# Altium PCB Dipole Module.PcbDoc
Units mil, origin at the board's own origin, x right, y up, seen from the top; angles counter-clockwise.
Board outline 1850 x 1950 mil, 2 copper layers (Top, Bottom), stack 62.8 mil thick; 30 components, 36 nets, 170 pads, 0 vias.
Unrouted connection lines stored in the file: 1.
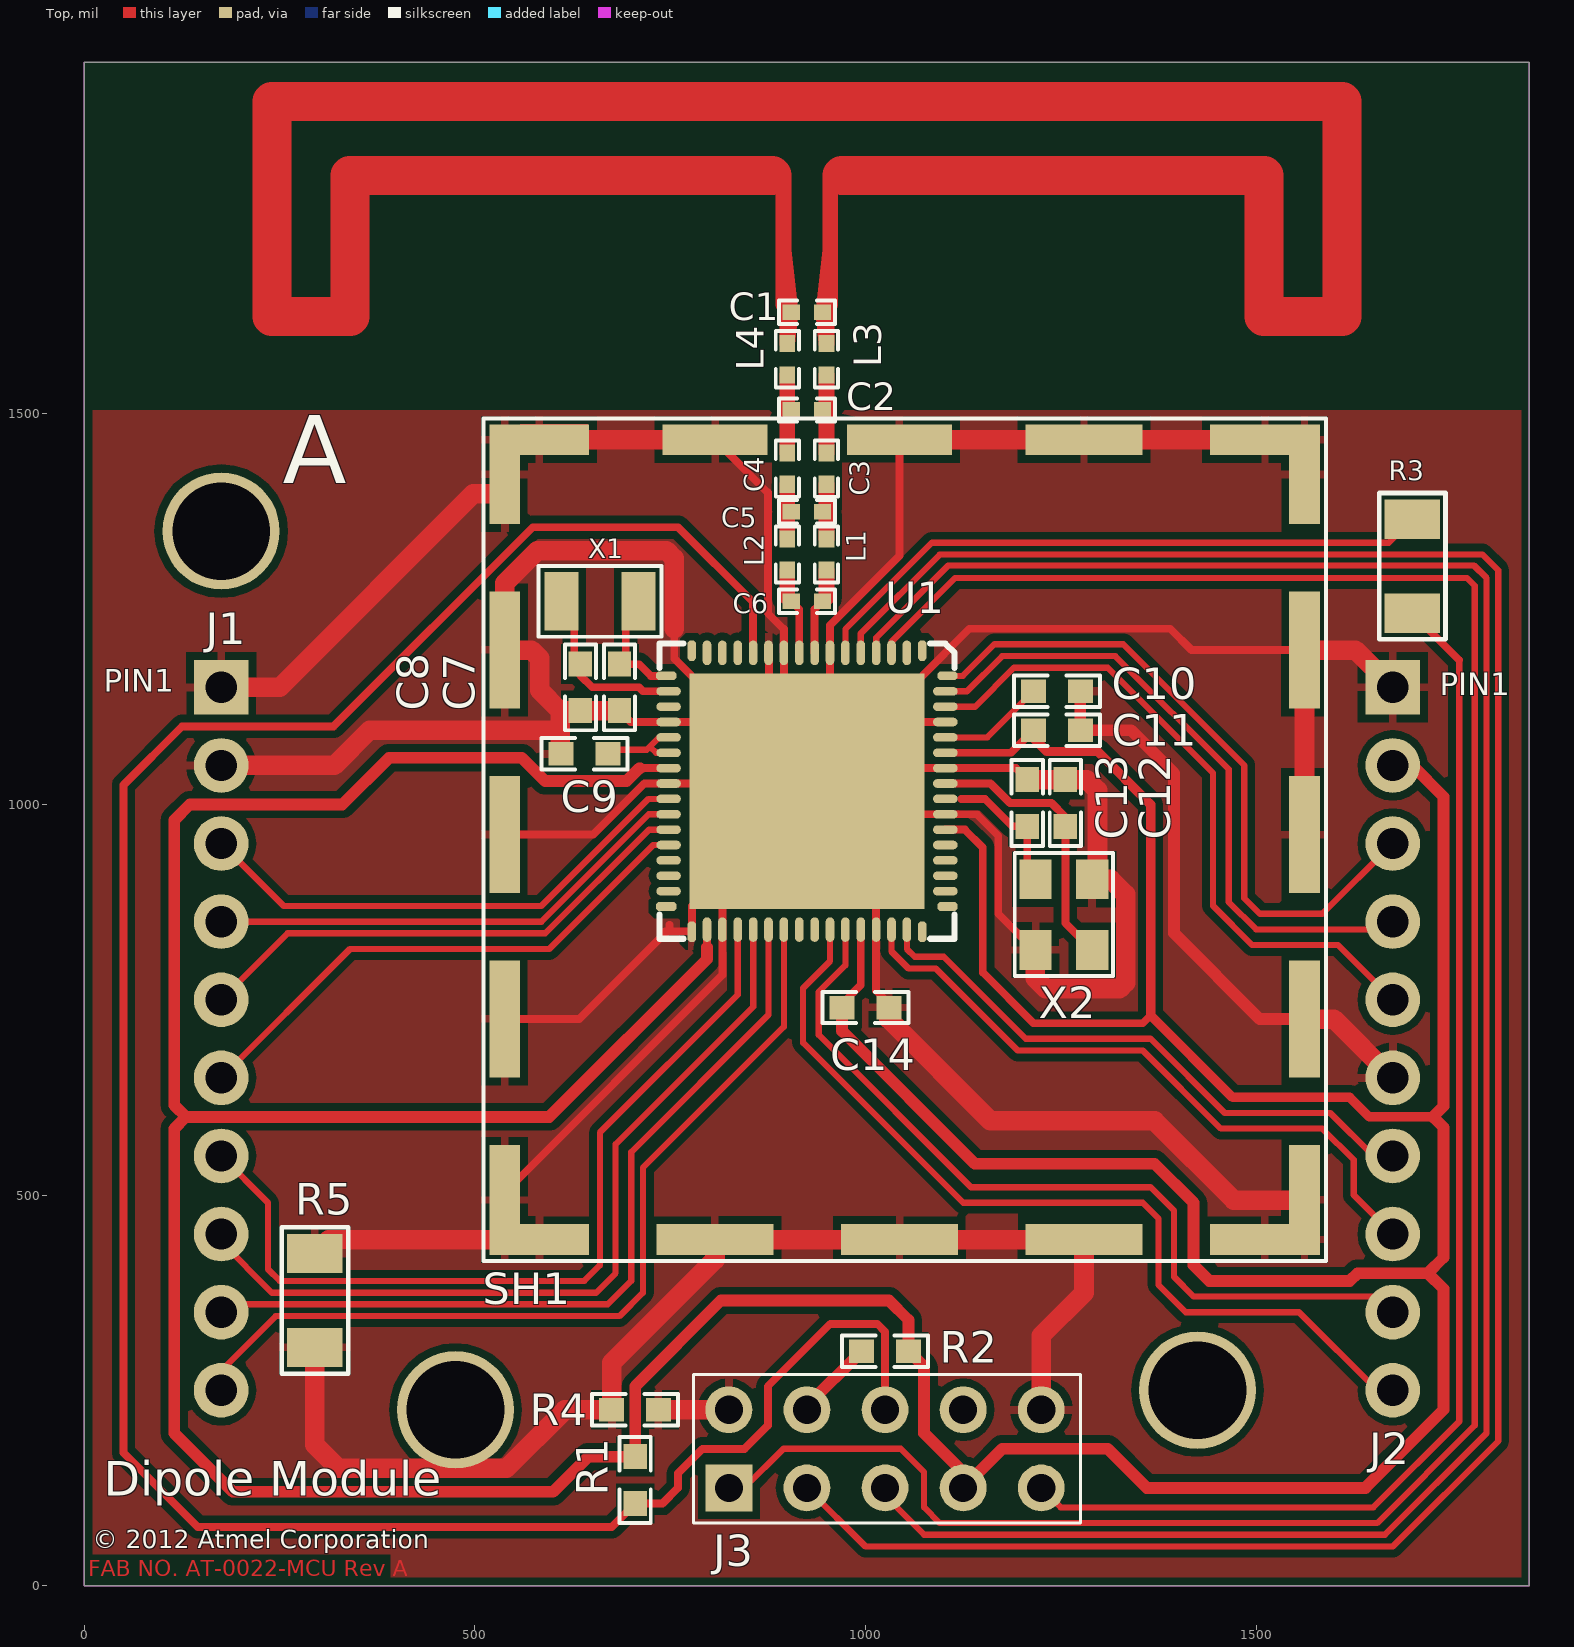
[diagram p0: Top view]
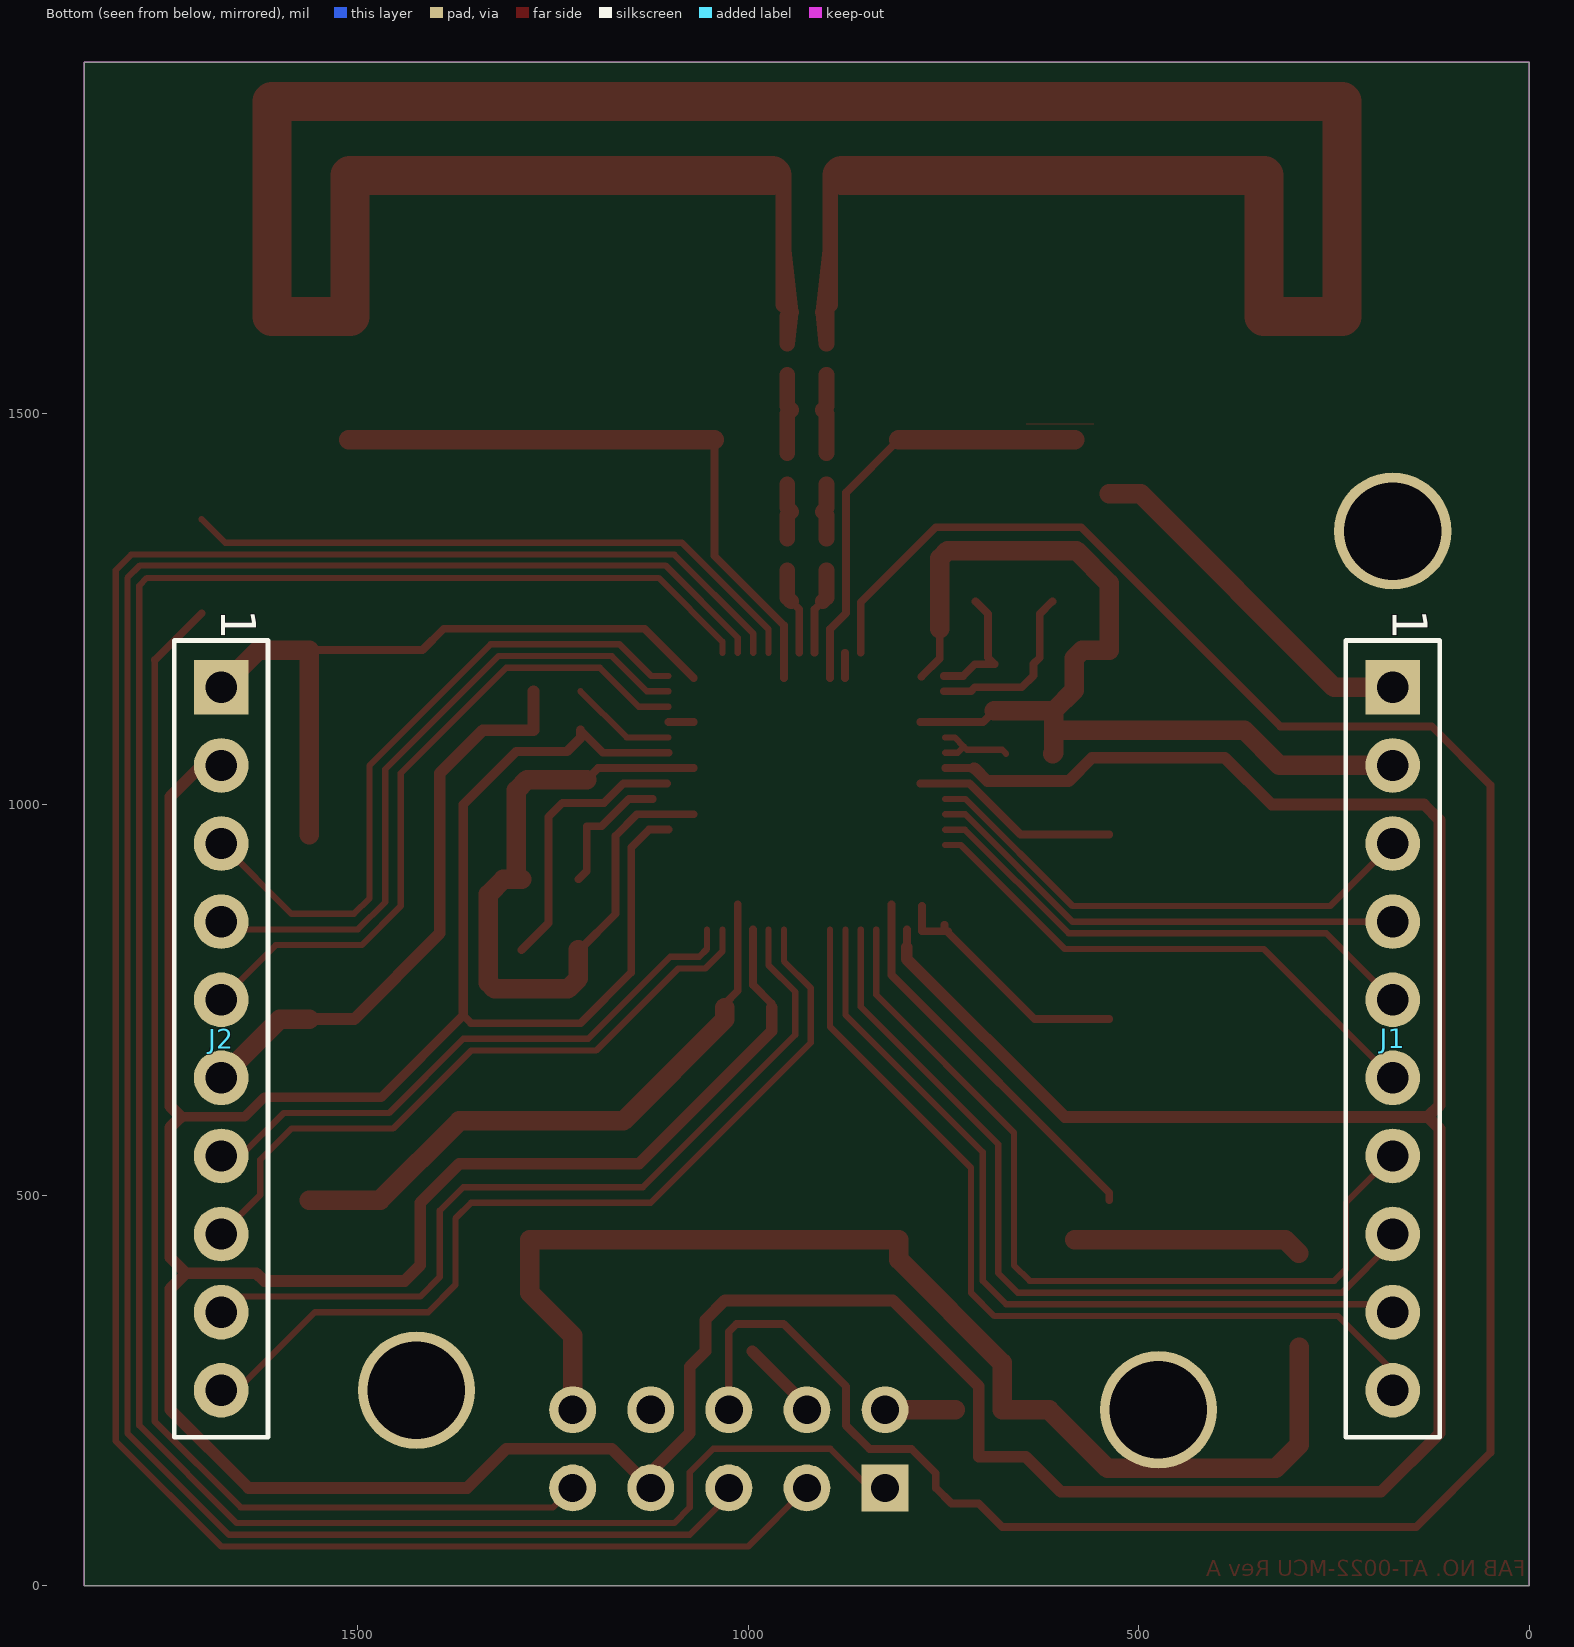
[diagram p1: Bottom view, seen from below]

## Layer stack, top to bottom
Top: signal copper 1.4
Dielectric: dielectric 60, FR-4, Dk 4
Bottom: signal copper 1.4

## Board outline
0,1950 1850,1950 1850,0 0,0

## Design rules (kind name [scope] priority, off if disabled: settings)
Clearance [All] p1: gap=10
DiffPairsRouting [All] p1 off: maxlimit=10 minlimit=10 mostfreqgap=10 maxuncoupledlength=500
FanoutControl Fanout_BGA [IsBGA] p1 off: bgadir=Out bgaviamode=Centered fanoutstyle=Auto fanoutdirection=Alternating viagrid=1 // Fanout_BGA (Default Rule)
FanoutControl Fanout_LCC [IsLCC] p2 off: bgadir=Out bgaviamode=Centered fanoutstyle=Auto fanoutdirection=Alternating viagrid=1 // Fanout_LCC (Default Rule)
FanoutControl Fanout_SOIC [IsSOIC] p3 off: bgadir=Out bgaviamode=Centered fanoutstyle=Auto fanoutdirection=Alternating viagrid=1 // Fanout_SOIC (Default Rule)
FanoutControl Fanout_Small [(CompPinCount < 5)] p4 off: bgadir=Out bgaviamode=Centered fanoutstyle=Auto fanoutdirection=OutThenIn viagrid=1 // Fanout_Small (Default Rule)
FanoutControl Fanout_Default [All] p5 off: bgadir=Out bgaviamode=Centered fanoutstyle=Auto fanoutdirection=Alternating viagrid=1 // Fanout_Default (Default Rule)
HoleSize [All] p1: absolutevalues=TRUE maxlimit=200 minlimit=1 maxpercent=80.000 minpercent=20.000
MinimumSolderMaskSliver [All] p1 off: minsoldermaskwidth=10
NetAntennae [All] p1 off: netantennaetolerance=0
PlaneConnect "Power Plane Connect Style - pads with no thermal" [(Name='J1-11') Or (Name='J1-12') Or (Name='J1-13') Or (Name='J1-14') Or (Name='J1-15') Or (Name='J1-16') Or (Name='J1-17') Or (Name='J1-18') Or (Name='J1-19') Or (Name='J1-20')] p1: planeconnectstyle=NoConnect reliefexpansion=20 reliefentries=4 reliefconductorwidth=10 reliefairgap=10 // PAD - No Thermal Connect Rule
PlaneConnect "Power Plane Connect Style - from global settings" [All] p2: planeconnectstyle=Relief reliefexpansion=20 reliefentries=2 reliefconductorwidth=8 reliefairgap=10
PolygonConnect [All] p1: connectstyle=Relief reliefconductorwidth=10 reliefentries=4 polygonreliefangle="90 Angle"
RoomDefinition "Dipole Module" [InComponentClass('Dipole Module')] p1: confinementstyle=ConfineIn formatcopy=TRUE lockcomponents=FALSE outline -9202.24,-8268.11 -7202.24,-8268.11 -7202.24,-7268.11 -9202.24,-7268.11
RoutingVias [All] p1: holewidth=28 width=50 viastyle="Through Hole" minholewidth=28 minwidth=50 maxholewidth=28 maxwidth=50
SilkToSilkClearance [All] p1: silktosilkclearance=1
SilkscreenOverComponentPads [All] p1 off: minsilkscreentomaskgap=10
SolderMaskExpansion "Solder Mask Expansion from CAM settings" [All] p1: expansion=2
Width [All] p1: maxlimit=100 minlimit=8 preferedwidth=10
16 further rules are at their usual default settings.

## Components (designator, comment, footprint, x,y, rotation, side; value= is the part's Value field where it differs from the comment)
C1 "NP" 0402 925,1630 r0 top
C2 "0.3pF" 0402 925,1505 r180 top
C3 "8.2pF" 0402 950,1430 r270 top locked
C4 "8.2pF" 0402 900,1430 r270 top locked
C5 "1pF" 0402-POL 925,1375 r180 top locked
C6 "0.7pF" 0402 925,1260 r180 top locked
C7 "12pF" 0603 685,1150 r270 top
C8 "12pF" 0603 635,1150 r270 top
C9 "X5R" 0603 640,1065 r180 top
C10 "X5R" 0603 1245,1145 r180 top
C11 "X5R" 0603 1245,1095 r180 top
C12 "12pF" 0603 1255.84,1001.84 r90 top
C13 "12pF" 0603 1207,1002 r270 top
C14 "X5R" 0603 1000,740 r0 top
J1 "Header 10" HDR1X10 175,1150 r270 bottom locked
J2 "Header 10" HDR1X10 1675,1150 r270 bottom locked
J3 "Header 5X2" HDR2X5 825,125 r90 top
L1 "LQG15HN2N7S02" 0402-POL 950,1320 r270 top locked
L2 "LQG15HN2N7S02" 0402-POL 900,1320 r270 top locked
L3 "LQG15HN1N0S02" 0402-POL 950,1570 r270 top
L4 "LQG15HN1N0S02" 0402-POL 900,1570 r270 top
R1 "0.5" 0603 705,135 r270 top
R2 "0.5" 0603 1025,300 r180 top
R3 "0.5" 1206_JUMPER 1700,1305 r90 top
R4 "0.5" 0603 705,225 r180 top
R5 "0.5" 1206_JUMPER 295,365 r90 top
SH1 "SHIELD" SHIELD_BMI-S-103_LAIRD 1050,955 r90 top locked
U1 "ATmega128RFA1-DE" MLF64-M2 925,1017 r90 top
X1 "32.768 KHZ" XTAL32_768KHZ_ABRACON 660,1260 r0 top
X2 "16.000 MHz 3.2 x 2.5 mm" XTAL16MHZKYOCERA 1254,859 r90 top

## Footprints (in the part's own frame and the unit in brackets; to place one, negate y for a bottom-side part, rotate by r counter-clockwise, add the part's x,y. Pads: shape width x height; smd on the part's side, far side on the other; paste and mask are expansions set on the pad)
0402 [mil]
  rect 22x20 smd: 1(-20,0) 2(20,0)
  silkscreen extent -36,-15 36,15
0402-POL [mil]
  rect 22x20 smd: 1(-20,0) 2(20,0)
  silkscreen extent -36,-15 36,15
0603 [mil]
  rect 32x30 smd: 1(-30,0) 2(30,0)
  silkscreen extent -55,-20 55,20
1206_JUMPER [mm]
  rect 1.27x1.8 smd: 1(-1.528,0.001) 2(1.528,-0.001)
  silkscreen extent -2.38,-1.08 2.38,1.08
HDR1X10 [mil] "HDR1X10"
  rect 70x70 hole 40: 1(0,0)
  round 70 hole 40: 2(100,0) 3(200,0) 4(300,0) 5(400,0) 6(500,0) 7(600,0) 8(700,0) 9(800,0) 10(900,0)
  silkscreen extent -60,-60 960,60
HDR2X5 [mil]
  rect 60x60 hole 36: 1(0,0)
  round 60 hole 36: 2(100,0) 3(0,-100) 4(100,-100) 5(0,-200) 6(100,-200) 7(0,-300) 8(100,-300) 9(0,-400) 10(100,-400)
  silkscreen extent -45,-450 145,45
MLF64-M2 [mm]
  oct 0.66x0.28 smd paste-0.03 mask+0: 1(4.572,-3.75) 16(4.572,3.75) 33(-4.572,3.75) 48(-4.572,-3.75)
  oval 0.8x0.28 smd paste-0.03 mask+0: 2(4.5,-3.25) 3(4.5,-2.75) 4(4.5,-2.25) 5(4.5,-1.75) 6(4.5,-1.25) 7(4.5,-0.75) 8(4.5,-0.25) 9(4.5,0.25) 10(4.5,0.75) 11(4.5,1.25) 12(4.5,1.75) 13(4.5,2.25) 14(4.5,2.75) 15(4.5,3.25) 34(-4.5,3.25) 35(-4.5,2.75) 36(-4.5,2.25) 37(-4.5,1.75) 38(-4.5,1.25) 39(-4.5,0.75) 40(-4.5,0.25) 41(-4.5,-0.25) 42(-4.5,-0.75) 43(-4.5,-1.25) 44(-4.5,-1.75) 45(-4.5,-2.25) 46(-4.5,-2.75) 47(-4.5,-3.25)
  oct 0.28x0.66 smd paste-0.03 mask+0: 17(3.75,4.572) 32(-3.75,4.572) 49(-3.75,-4.572) 64(3.75,-4.572)
  oval 0.28x0.8 smd paste-0.03 mask+0: 18(3.25,4.5) 19(2.75,4.5) 20(2.25,4.5) 21(1.75,4.5) 22(1.25,4.5) 23(0.75,4.5) 24(0.25,4.5) 25(-0.25,4.5) 26(-0.75,4.5) 27(-1.25,4.5) 28(-1.75,4.5) 29(-2.25,4.5) 30(-2.75,4.5) 31(-3.25,4.5) 50(-3.25,-4.5) 51(-2.75,-4.5) 52(-2.25,-4.5) 53(-1.75,-4.5) 54(-1.25,-4.5) 55(-0.75,-4.5) 56(-0.25,-4.5) 57(0.25,-4.5) 58(0.75,-4.5) 59(1.25,-4.5) 60(1.75,-4.5) 61(2.25,-4.5) 62(2.75,-4.5) 63(3.25,-4.5)
  rect 7.65x7.65 smd paste-2.8 mask+0: 65(0,0)
  silkscreen extent -4.8,-4.8 4.8,4.8
SHIELD_BMI-S-103_LAIRD [mm]
  rect 1x3.57 smd: 1(-13.005,-11.72) 5(13.005,-11.72)
  rect 3.57x1 smd: 1(-11.72,-13.005) 13(-11.72,13.005)
  rect 3.8x1 smd: 2(-5.835,-13.005) 3(0.165,-13.005) 4(6.165,-13.005) 10(6.165,13.005) 11(0.165,13.005) 12(-5.835,13.005)
  rect 3.24x1 smd: 5(11.885,-13.005) 9(11.885,13.005)
  rect 1x3.8 smd: 6(13.005,-5.835) 14(-13.005,6.165) 15(-13.005,0.165) 16(-13.005,-5.835)
  rect 1x3.4 smd: 7(13.005,0.165) 8(13.005,6.165)
  rect 1x3.24 smd: 9(13.005,11.885) 13(-13.005,11.885)
  Top lines w0.001: 13.505,12.505 13.505,10.305
  silkscreen extent -13.7,-13.7 13.7,13.7
XTAL16MHZKYOCERA [mm]
  rect 1.3x1.05 smd: 1(-1.15,0.925) 2(-1.15,-0.925) 3(1.15,0.925) 4(1.15,-0.925)
  silkscreen extent -2,-1.6 2,1.6
XTAL32_768KHZ_ABRACON [mm]
  rect 1.1x1.9 smd: 1(-1.25,0) 2(1.25,0)
  silkscreen extent -2,-1.15 2,1.15

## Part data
C1: "CAP CER NP"
C2: "CAP CER 3PF"
C3 C4: "CAP CER 82PF"
C5: "CAP CER 1PF"
C6: "CAP CER 7PF"
C7 C8 C9 C10 C11 C12 C13 C14: "CAP CER 15PF"
J1 J2: "Header, 10-Pin"
J3: "Header, 5-Pin, Dual row"
L1 L2: library part "INDUCTOR SHIELD PWR 27nH", "27nH"
L3: library part "INDUCTOR SHIELD PWR 10nH", "1.0nH"
L4: library part "INDUCTOR SHIELD PWR 10nH", "10nH"
R1 R2 R3 R4 R5: "RES .50 OHM 1W 1% 2512 SMD"
SH1: library part "Header 16H", "Header, 16-Pin, Right Angle"
U1: "802.15.4 compliant AVR transceiver"
X1: library part XTAL, "CRYSTAL 32.768KHZ 12.5PF SMD"
X2: "CRYSTAL 16MHZ 8PF SMD"

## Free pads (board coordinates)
  round 150 hole 125: 0(175,1350) 0(475,225) 0(1425,250)

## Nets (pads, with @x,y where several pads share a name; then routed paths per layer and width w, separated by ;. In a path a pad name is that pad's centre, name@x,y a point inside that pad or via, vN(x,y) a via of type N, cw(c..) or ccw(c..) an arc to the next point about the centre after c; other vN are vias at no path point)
AGND: C7.2 C8.2 C9.2 C10.1 C11.1 C12.2 C13.1 C14.2 J1.1 J1.2 J2.1 J2.6 J3.2 J3.10 R4.1 R4.2 R5.1 R5.2 SH1.1 SH1.2 SH1.3 SH1.4 SH1.5 SH1.6 SH1.7 SH1.8 SH1.9 SH1.10 SH1.11 SH1.12 SH1.13 SH1.14 SH1.15 SH1.16 U1.7 U1.10 U1.11 U1.20 U1.24 U1.33 U1.35 U1.45 U1.55 U1.58 U1.61 U1.65 X2.1 X2.4 | length 9605.6
  Top w10: SH1.13@537.99,493.58 537.99,502.99 816.73,781.73 U1.35 U1.65@816.73,872 ; SH1.12 633,725.28 ; SH1.11 651.5,961.5 716.84,1026.84 U1.24 U1.65@780,1026.84 ; 633.14,725.14 749,841 749,846 ; C7.2 699.42,1105.58 U1.20 U1.65@780,1105.58 ; 744,837.73 U1.33@776.17,837.73 ; 755,1225 755,1187 U1.65@778.5,1163.5 ; U1.33@777.73,837.83 U1.65@777.73,870 ; SH1.8 875,1399.29 875,1245 895.47,1224.53 U1.10 U1.65@895.47,1162 ; U1.65@876.47,1162 U1.11@876.47,1194.16 ; U1.65@954.53,1162 U1.7 954.53,1229.53 1043.5,1318.5 SH1.7 ; U1.65@1013.58,872 U1.45 1013.58,761.42 1030,745 C14.2 ; U1.65@1070,987.47 U1.55 1142.53,987.47 1170,960 1170,860 1216.28,813.72 X2.1 ; U1.65@1070,1046.53 U1.58 1192.47,1046.53 C13.1 ; U1.65@1070,1105.58 U1.61 ; U1.65@1070,1162 1133,1225 1390,1225 1417.28,1197.72 SH1.4
  Top w15: C10.1 C11.1 1340,1095 1395,1040 1395,835 1504.72,725.28 SH1.2
  Top w25: J1.2 320,1050 365,1095 609,1095 ; J1.1 250,1150 497.91,1397.91 SH1.9@537.99,1397.91 ; R5.1 294.94,180.06 325,150 540,150 615,225 R4.2 675,285 807.28,417.28 SH1.14 SH1.16 1279.72,374.72 1225,320 J3.10 ; R5.2 312.89,442.99 SH1.13@582.09,442.99 ; SH1.9@582.09,1467.01 SH1.8 ; C9.2 609,1066 609,1095 ; C7.2 609,1120 ; R4.1 J3.2 ; 755,1225 755,1315 745,1325 580,1325 537.99,1282.99 SH1.10 572.28,1197.72 582.72,1187.28 582.72,1146.28 609,1120 ; C14.2 1030,725 1160,595 1370,595 1471.42,493.58 SH1.1@1562.01,493.58 ; SH1.7 SH1.5@1511.42,1467.01 ; C13.1@1207,1031.84 1283.16,1031.84 1297,1018 1297,910.86 X2.4 1313.72,904.28 1333,885 1333,772 1325,764 1231,764 1217.58,777.42 X2.1 ; SH1.2 1599.72,725.28 J2.6 ; SH1.3 SH1.4 1627.28,1197.72 J2.1 ; 609,1095 609,1120
NetC1_1: C1.1 C1.2 L3.1 L4.1 | length 4425.6
  Top w8: C1.2 C1.2@950,1625
  Top w20: 880,1805 895,1805 895,1640 C1.1@902.5,1632.5 ; 895,1709.43 C1.1@904,1630 ; C1.1 C1.1@902.5,1632.5 ; C1.2 955,1640 955,1805 970,1805 ; 955,1709.43 C1.2@946,1630 ; C1.1@900,1630 L4.1 C1.1@904,1630 ; C1.1@900,1630 900,1591 C1.1@904,1630 ; C1.1@900,1630 C1.1@902.5,1632.5 ; C1.2@946,1630 L3.1 950,1625 950,1591 C1.2@946,1630
  Top w50: 880,1805 340,1805 340,1625 240,1625 240,1900 1610,1900 1610,1625 1510,1625 1510,1805 970,1805
NetC2_1: C2.1 C3.1 L3.2 | length 104.1
  Top w20: C3.1 950,1500 C2.1 950,1510 L3.2
NetC2_2: C2.2 C4.1 L4.2 | length 104.1
  Top w20: C4.1 900,1500 C2.2 900,1510 L4.2
NetC3_2: C3.2 C5.1 L1.1 | length 74.1
  Top w20: L1.1 950,1370 C5.1 950,1380 C3.2
NetC4_2: C4.2 C5.2 L2.1 | length 74.1
  Top w20: L2.1 900,1370 C5.2 900,1380 C4.2
NetC6_1: C6.1 L1.2 U1.8 | length 112.1
  Top w10: U1.8 934.84,1249.84 C6.1
  Top w20: C6.1 950,1265 L1.2
NetC6_2: C6.2 L2.2 U1.9 | length 112.1
  Top w10: C6.2 915.16,1249.84 U1.9
  Top w20: L2.2 900,1265 C6.2
NetC7_1: C7.1 U1.17 X1.2 | length 162.2
  Top w10: X1.2 693,1243.79 693,1188 C7.1 684.5,1179.5 710.14,1179.5 725,1164.64 U1.17@749.83,1164.64
NetC8_1: C8.1 U1.18 X1.1 | length 228.2
  Top w10: X1.1 627,1243.79 627,1188 C8.1 635,1165 650,1150 709.95,1150 715,1144.95 U1.18 U1.18@749.84,1144.95
NetC9_1: C9.1 U1.21 U1.22 | length 113.6
  Top w8: C9.1 675,1070 720,1070 724,1074 ; U1.22 731.79,1066.21 724,1074 ; U1.21 735.9,1085.9 724,1074
NetC10_2: C10.2 U1.60 | length 137.3
  Top w8: U1.60 1155.9,1085.9 C10.2
NetC12_1: C12.1 U1.57 X2.2 | length 354.1
  Top w10: U1.57@1104.17,1026.84 1160,1026.84 1185,1001.84 1238.16,1001.84 1255.84,984.16 C12.1 1255.84,848.3 X2.2
NetC13_2: C13.2 U1.56 X2.3 | length 171.2
  Top w10: 1122.5,1007.16 1152.84,1007.16 1188,972 C13.2 1207,914.86 X2.3
NetJ1_3: J1.3 U1.25 | length 662.8
  Top w8: J1.3 255,870 585,870 722.16,1007.16 U1.25
NetJ1_4: J1.4 U1.26 | length 629.8
  Top w8: J1.4 585,850 722.47,987.47 U1.26
NetJ1_5: J1.5 U1.27 | length 663
  Top w8: J1.5 260,835 590,835 722.79,967.79 U1.27
NetJ1_6: J1.6 U1.28 | length 696.3
  Top w8: J1.6 340,815 595,815 728.1,948.1 U1.28
NetJ1_7: J1.7 U1.36 | length 1112.3
  Top w8: J1.7 235,490 235,405 250,390 640,390 660,410 660,580 836.42,756.42 U1.36
NetJ1_8: J1.8 U1.37 | length 1065.1
  Top w8: J1.8 175,440 240,375 655,375 680,400 680,565 856.1,741.1 U1.37
NetJ1_9: J1.9 U1.38 | length 1064.2
  Top w8: J1.9 185,360 670,360 700,390 700,555 875.79,730.79 U1.38
NetJ1_10: J1.10 U1.39 | length 1146
  Top w8: J1.10 175,275 245,345 685,345 715,375 715,535 895.47,715.47 U1.39
NetJ2_3: J2.3 U1.64 | length 869.3
  Top w8: U1.64@1102.17,1164.64 U1.64 1124.64,1164.64 1165,1205 1330,1205 1485,1050 1485,880 1505,860 1585,860 J2.3
NetJ2_4: J2.4 U1.63 | length 840.2
  Top w8: U1.63 1129.95,1144.95 1175,1190 1320,1190 1465,1045 1465,875 1500,840 1665,840 J2.4
NetJ2_5: J2.5 U1.62 | length 869.1
  Top w8: U1.62 1140.27,1125.27 1190,1175 1310,1175 1445,1040 1445,870 1495,820 1605,820 J2.5
NetJ2_7: J2.7 U1.47 | length 756.6
  Top w8: U1.47 1052.95,815 1062.95,805 1100,805 1205,700 1365,700 1460,605 1595,605 1650,550 J2.7
NetJ2_8: J2.8 U1.46 | length 846
  Top w8: U1.46 1033.27,811.73 1055,790 1090,790 1195,685 1355,685 1455,585 1585,585 1625,545 1625,500 J2.8
NetJ2_9: J2.9 U1.43 | length 1080.8
  Top w8: U1.43 974.21,794.21 940,760 940,705 1135,510 1365,510 1395,480 1395,395 1420,370 1655,370 J2.9
NetJ2_10: J2.10 U1.42 | length 1148.3
  Top w8: U1.42 954.53,799.53 920,765 920,695 1125,490 1355,490 1375,470 1375,385 1410,350 1555,350 1655,250 J2.10
NetJ3_6: J3.6 R1.2 U1.12 | length 3168.8
  Top w10: U1.12 856.1,1258.9 760,1355 573.94,1355 318.94,1100 125,1100 50,1025 50,170 145,75 675,75 R1.2 740,105 760,125 760,143.75 791.25,175 845,175 875,205 875,255 955,335 1015,335 1025,325 J3.6
NetR3_2: R3.2 U1.6 | length 814.3
  Top w8: U1.6 974.21,1224.21 1085,1335 1669.89,1335 R3.2
TCK: J3.1 U1.3 | length 2967
  Top w8: J3.1 845,125 895,175 1045,175 1075,145 1075,100 1095,80 1655,80 1780,205 1780,1280 1770,1290 1115,1290 1033.27,1208.27 U1.3
TDI: J3.9 R3.1 | length 1650.6
  Top w8: J3.9 1250,100 1650,100 1760,210 1760,1184.78
  Top w10: R3.1 1760,1184.78
TDO: J3.3 U1.5 | length 2978
  Top w8: J3.3 1000,50 1675,50 1810,185 1810,1300 1790,1320 1095,1320 993.9,1218.9 U1.5
TMS: J3.5 U1.4 | length 2795.3
  Top w8: U1.4 1013.58,1213.58 1106,1306 1779,1306 1795,1290 1795,195 1665,65 1075,65 1025,115 J3.5
VDD: C11.2 C14.1 J2.2 J3.4 J3.7 R1.1 R2.1 R2.2 U1.23 U1.34 U1.44 U1.54 U1.59 | length 7888.9
  Top w10: 711.53,1046.53 U1.23 ; 797.05,817.05 U1.34 ; C14.1 970,745 993.9,768.9 U1.44 ; U1.54 1127.21,967.79 1150,945 1150,785 1215,720 1355,720 1365,730 ; U1.59 1186.21,1066.21 C11.2
  Top w12: C11.2 1215,1085 1232.18,1067.82 1297.18,1067.82 1365,1000 1365,730 1470,625 1620,625 1645,600 1726.5,600
  Top w15: 711.53,1046.53 710.36,1046.53 693.84,1030 590,1030 560,1060 390,1060 330,1000 135,1000 115,980 115,615 130,600 ; 797.05,817.05 797.05,802.05 595,600 130,600 ; J3.4 925,230 R2.2 ; C14.1 970,710 1140,540 1370,540 1420,490 1420,410 1440,390 1620,390 1630,400 1720,400 ; J2.2 1700,1050 1740,1010 1740,613.5 1726.5,600 1740,586.5 1740,420 1720,400 ; 130,600 115,585 115,195 190,120 600,120 645,165 R1.1 705,255 815,365 1030,365 1055,340 R2.1 1075,280 1075,195 1125,145 J3.7 1175,175 1310,175 1360,125 1640,125 1740,225 1740,380 1720,400
pads on no net: J3.8 U1.1 U1.2 U1.13 U1.14 U1.15 U1.16 U1.19 U1.29 U1.30 U1.31 U1.32 U1.40 U1.41 U1.48 U1.49 U1.50 U1.51 U1.52 U1.53

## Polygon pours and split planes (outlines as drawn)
AGND on Top "Top-GND" (solid, remove dead copper, pour order 2): 0,1505 1850,1505 1850,0 0,0

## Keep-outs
Keep-Out Layer:
  the board outline again, w1

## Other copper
Top:
  text "FAB NO. AT-0022-MCU Rev A" at 5,5 h35
  text "TOP LAYER" at 0,-320 h60

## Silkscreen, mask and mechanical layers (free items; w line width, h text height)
Silkscreen Top:
  text "A" at 253.91,1382.69 h150
  text "PIN1" at 25,1135 h50
  text "PIN1" at 1735,1130 h50
  text "Dipole Module" at 25,100 h76
  text "© 2012 Atmel Corporation" at 10.71,40.11 h40
  text "TOP SILKSCREEN" at 0,-220 h60
Paste Mask Top:
  text "TOP PASTE" at 1000,-220 h60
Paste Mask Bottom:
  text "BOTTOM PASTE" at 1000,-320 h60
Solder Mask Top:
  text "TOP SOLDERMASK" at 1000,-420 h60
Solder Mask Bottom:
  text "BOTTOM SOLDERMASK" at 1000,-520 h60
Assembly Drawing Top:
  lines w1: -15,480 140,480 ; -15,1950 140,1950 ; 35,1082.05 35,480 ; 35,1347.95 35,1950 ; 190,335 190,430 ; 792.05,385 190,385 ; 925,1875 265,1875 265,1650 315,1650 315,1830 905,1830 ; 925,1880 1585,1880 1585,1650 1535,1650 1535,1830 945,1830 ; 1057.95,385 1660,385 ; 1660,335 1660,430 ; 35,480 15,540 55,540 35,480 ; 35,1950 55,1890 15,1890 35,1950 ; 190,385 250,405 250,365 190,385 ; 190,480 190.03,480 ; 190,480 190.03,480 ; 885,1780 885,1660 885,1780 ; 885,1780 365,1780 365,1600 215,1600 215,1925 925,1925 1635,1925 1635,1600 1485,1600 1485,1780 965,1780 ; 905,1830 905,1660 905,1830 ; 945,1830 945,1660 945,1830 ; 965,1780 965,1660 965,1780 ; 1660,385 1600,365 1600,405 1660,385 ; 190,1950 190.03,1950 ; 1660,480 1660.03,480
  text "TOP SIDE ASSEMBLY NOTES:" at -200,2900 h70
  text "1. THE FOLLOWING COMPONENTS CAN BE POPULATED IN EITHER ORIENTATION:" at -300,2800 h50
  text "ALL RESISTORS AND NON-POLARIZED CAPACITORS" at -200,2700 h50
  text "CRYSTAL X2" at 1600,2700 h50
  text "CONNECTOR J1" at -200,2600 h50
  text "RF SHIELD SHD1" at 400,2600 h50
  text "2. WATCH FOR POLARITY OR ORIENTATION MARKINGS ON THE FOLLOWING COMPONENTS:" at -300,2500 h50
  text "INDUCTORS L1-L4" at -200,2400 h50
  text "INTEGRATED CIRCUIT U1" at 500,2400 h50
  text "3. FINISHED ASSEMBLY NEEDS TO BE RoHS COMPLIANT." at -300,2300 h50
  text "4. POPULATE CRYSTAL X1 (BOTTOM SIDE) OR X2 (TOP SIDE) BUT NOT BOTH." at -300,2200 h50
  text "1.470\"" at 57.5,1142.05 h30 r90
  text "9" at 750,715 h25
  text "1" at 1085,715 h25
  text "10" at 740,660 h25
  text "2" at 1085,660 h25
  text "1.470\"" at 852.05,362.5 h30
guidance:
  lines w1: 520,653 1335,653 ; 825,405 825,1055 ; 925,400 925,2005
Drill Drawing:
  rectangle: 3925,2317 4275,2325
  rectangle: 3925,2625 4275,2675
  lines w1: 0,0 1850,0 1850,1950 0,1950 0,0
  lines w6: 1375,-1700 1375,-700 5800,-700.48 ; 2250,-1700 2250,-700 ; 2250,-1550 5400,-1550 ; 2250,-1300 5400,-1300 ; 2250,-1000.48 5800,-1000.48 ; 3110,-1700 3110,-1550 ; 4275,-1700 4275,-1550 ; 5400,-1700 5400,-1000 ; -400,-1700 -400,3100 5800,3100 5800,-1700 -400,-1700
  lines w8: 3375,2325 3875,2325 ; 3375,2625 3875,2625 ; 3650,2300 3675,2325 ; 3650,2650 3675,2625 ; 3675,2215 3675,2325 ; 3675,2825 3675,2625 ; 3700,2300 3675,2325 ; 3700,2650 3675,2625 ; 4325,2325 5150,2325 ; 4325,2625 5150,2625
  text "DETAIL A" at 3905,2885 h75
  text "TOP LAYER .GTL" at 4425,2675 h50
  text "62 MILS" at 3175,2425 h50
  text "NOTES: (UNLESS SPECIFIED UNITS ARE IN INCHES)" at 2200,2050 h75
  text "1. FABRICATE BOARD PER IPC-A-600C" at 2100,1900 h60
  text "2. MATERIAL FR-4, LAYERS 2" at 2100,1800 h60
  text "3. BOARD THICKNESS: 0.062 +/-10%" at 2100,1700 h60
  text "4. PROVIDE THE PROPER DIELECTRIC FOR ALL LAYERS" at 2100,1600 h60
  text "5. MINIMUM PLATING ON THROUGH HOLE SHALL BE 0.001 INCH Cu" at 2100,1500 h60
  text "6. 1/2 OZ. ON TOP & BOTTOM LAYERS" at 2100,1400 h60
  text "7. FINISH: ELECTROLESS NICKEL IMMERSION GOLD" at 2100,1300 h60
  text "8. ALL HOLES ARE PLATED THROUGH UNLESS OTHERWISE SPECIFIED" at 2100,1200 h60
  text "9. HOLE SIZES ARE FINISHED SIZE" at 2100,1100 h60
  text "10. SOLDER MASK BOTH SIDES WITH BLUE LPI" at 2050,1000 h60
  text "11. FOR LAYER STACK SEE DETAIL A." at 2050,900 h60
  text "12. SILKSCREEN BOTH SIDES USING \"WHITE EPOXY\" OVER SOLDER MASK" at 2050,800 h60
  text "13. DEBURR ALL SHARP EDGES." at 2050,700 h60
  text "14. OVERALL BOARD BOW SHOULD NOT EXCEED 0.01" at 2050,600 h60
  text "DRILL TABLE" at 2400,400 h100
  text ".LEGEND" at 2100,-500 h65
  text "Dipole Module" at 2451,-892 h100
  text "A" at 1408.23,-1155.48 h500
  text "FAB NO. AT-0022-MCU" at 2471,-1199 h100
  text "REV." at 5500,-1300 h80
  text "1600 Technology Drive" at 1398.23,-1320.48 h40
  text "San Jose, CA 95110" at 1398.23,-1420.48 h40
  text "A" at 5575,-1500 h80
  text "www.atmel.com" at 1398.23,-1520.48 h40
  text "DATE: Jul 02, 2012" at 2260,-1655 h45
  text "ENGINEER :" at 3135,-1655 h45
  text "DESIGNER : PAUL ESPIRITU" at 4313.23,-1655.48 h45

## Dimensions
0,1950 to 1850,1950 on Drill Drawing
0,0 to 0,1950 on Drill Drawing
